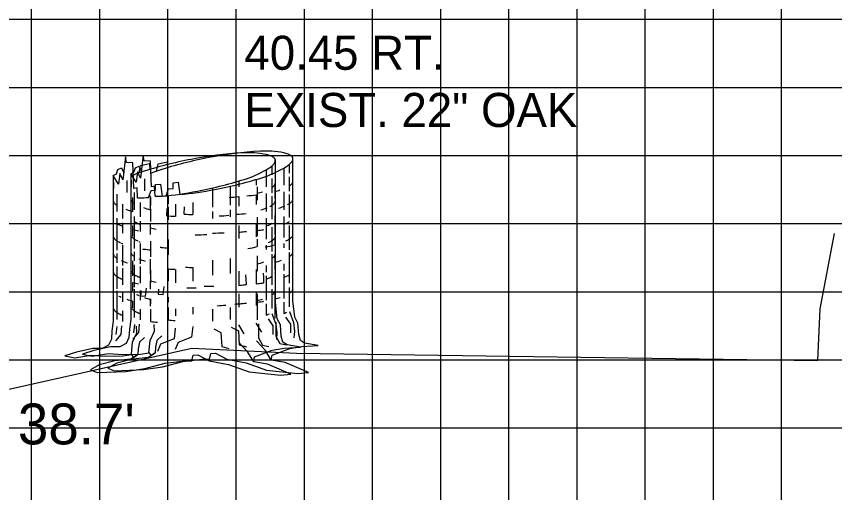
# Model space of a CAD drawing. Extents: x 853785 to 853955, y 366268 to 366378.
# Drawn here: x 853907.21 to 853919.21, y 366284.29 to 366291.28 of the extents above; entities that cross this region are included whole.
import ezdxf

# ---------------------------------------------------------------- set-up
doc = ezdxf.new("R2010")
doc.units = 0
for name, color, linetype in [('D_Text_Monospaced', 7, 'Continuous'), ('D_Text_Standard', 7, 'Continuous'), ('MAJOR', 7, 'Continuous'), ('MINOR', 7, 'Continuous'), ('S_Roadway_Centerline', 7, 'Continuous'), ('S_Trees_Decid_Pay', 7, 'Continuous')]:
    doc.layers.add(name, color=color, linetype=linetype)

msp = doc.modelspace()

# ---------------------------------------------------------------- linework, layer by layer
at = {"layer": 'MAJOR'}
for p, q in [((853908.435, 366277.236), (853908.435, 366297.236)), ((853913.435, 366277.236), (853913.435, 366297.236)), ((853918.435, 366277.236), (853918.435, 366297.236)), ((853798.435, 366287.236), (853938.435, 366287.236))]:
    msp.add_line(p, q, dxfattribs=at)
at = {"layer": 'MINOR'}
for p, q in [((853907.435, 366277.236), (853907.435, 366297.236)), ((853909.435, 366277.236), (853909.435, 366297.236)), ((853910.435, 366277.236), (853910.435, 366297.236)), ((853911.435, 366277.236), (853911.435, 366297.236)), ((853912.435, 366277.236), (853912.435, 366297.236)), ((853914.435, 366277.236), (853914.435, 366297.236)), ((853915.435, 366277.236), (853915.435, 366297.236)), ((853916.435, 366277.236), (853916.435, 366297.236)), ((853917.435, 366277.236), (853917.435, 366297.236)), ((853798.435, 366291.236), (853938.435, 366291.236)), ((853798.435, 366290.236), (853938.435, 366290.236)), ((853798.435, 366289.236), (853938.435, 366289.236)), ((853798.435, 366288.236), (853938.435, 366288.236)), ((853798.435, 366286.236), (853938.435, 366286.236)), ((853798.435, 366285.236), (853938.435, 366285.236))]:
    msp.add_line(p, q, dxfattribs=at)
at = {"layer": 'S_Roadway_Centerline'}
msp.add_lwpolyline([(853837.576, 366284.644), (853850.621, 366285.197), (853857.775, 366285.567), (853862.721, 366285.439), (853868.661, 366285.302), (853871.998, 366285.204), (853882.091, 366284.926), (853892.253, 366284.386), (853893.703, 366284.334), (853894.544, 366284.353), (853894.551, 366284.361), (853894.991, 366284.732), (853895.13, 366284.733), (853902.757, 366284.942), (853904.091, 366285.128), (853909.786, 366286.408), (853911.32, 366286.334), (853918.965, 366286.226), (853919.002, 366286.986), (853919.212, 366288.09)], dxfattribs=at)
at = {"layer": 'S_Trees_Decid_Pay'}
for p, q in [((853910.957, 366289.071), (853910.957, 366288.951)), ((853911.214, 366289.096), (853911.214, 366288.975)), ((853910.877, 366289.027), (853910.877, 366288.773)), ((853911.134, 366289.052), (853911.134, 366288.798)), ((853908.832, 366288.868), (853908.832, 366288.693)), ((853909.09, 366288.893), (853909.09, 366288.718)), ((853910.472, 366288.86), (853910.472, 366288.773)), ((853910.73, 366288.885), (853910.73, 366288.798)), ((853910.957, 366288.899), (853910.957, 366288.685)), ((853911.214, 366288.924), (853911.214, 366288.71)), ((853910.089, 366288.759), (853910.089, 366288.479)), ((853910.346, 366288.784), (853910.346, 366288.504)), ((853910.745, 366288.773), (853910.745, 366288.582)), ((853911.002, 366288.798), (853911.002, 366288.607)), ((853908.683, 366288.668), (853908.683, 366288.413)), ((853908.917, 366288.619), (853908.917, 366288.414)), ((853908.94, 366288.693), (853908.94, 366288.438)), ((853909.174, 366288.644), (853909.174, 366288.439)), ((853909.178, 366288.621), (853909.178, 366288.502)), ((853909.436, 366288.646), (853909.436, 366288.527)), ((853910.472, 366288.632), (853910.472, 366288.493)), ((853910.73, 366288.657), (853910.73, 366288.518)), ((853910.877, 366288.677), (853910.877, 366288.413)), ((853910.957, 366288.64), (853910.957, 366288.302)), ((853911.134, 366288.702), (853911.134, 366288.438)), ((853911.214, 366288.664), (853911.214, 366288.327)), ((853908.769, 366288.522), (853908.769, 366288.31)), ((853909.026, 366288.547), (853909.026, 366288.335)), ((853909.436, 366288.475), (853909.436, 366288.29)), ((853909.543, 366288.522), (853909.543, 366288.342)), ((853909.674, 366288.374), (853909.679, 366288.481)), ((853909.8, 366288.547), (853909.8, 366288.367)), ((853909.178, 366288.45), (853909.178, 366288.265)), ((853909.416, 366288.35), (853909.422, 366288.456)), ((853910.089, 366288.413), (853910.089, 366288.31)), ((853910.346, 366288.438), (853910.346, 366288.335)), ((853911.002, 366288.355), (853911.002, 366288.078)), ((853908.683, 366288.316), (853908.683, 366287.847)), ((853908.769, 366288.245), (853908.769, 366288.096)), ((853908.94, 366288.341), (853908.94, 366287.872)), ((853909.026, 366288.269), (853909.026, 366288.121)), ((853909.174, 366288.232), (853909.174, 366288.078)), ((853910.73, 366288.232), (853910.73, 366288.04)), ((853910.745, 366288.331), (853910.745, 366288.053)), ((853910.877, 366288.316), (853910.877, 366288.008)), ((853911.134, 366288.341), (853911.134, 366288.033)), ((853908.917, 366288.207), (853908.917, 366288.053)), ((853910.472, 366288.207), (853910.472, 366288.016)), ((853910.957, 366288.185), (853910.957, 366287.824)), ((853911.214, 366288.21), (853911.214, 366287.849)), ((853909.436, 366288.004), (853909.436, 366287.775)), ((853910.745, 366288.008), (853910.745, 366287.899)), ((853911.002, 366288.033), (853911.002, 366287.924)), ((853908.769, 366287.919), (853908.769, 366287.619)), ((853909.026, 366287.944), (853909.026, 366287.643)), ((853909.178, 366287.979), (853909.178, 366287.75)), ((853910.877, 366287.919), (853910.877, 366287.853)), ((853911.134, 366287.944), (853911.134, 366287.878)), ((853908.683, 366287.796), (853908.683, 366287.662)), ((853908.94, 366287.821), (853908.94, 366287.687)), ((853910.745, 366287.764), (853910.745, 366287.536)), ((853910.957, 366287.787), (853910.957, 366287.338)), ((853911.002, 366287.789), (853911.002, 366287.561)), ((853911.214, 366287.812), (853911.214, 366287.363)), ((853908.917, 366287.69), (853908.917, 366287.47)), ((853908.94, 366287.629), (853908.94, 366287.304)), ((853909.174, 366287.715), (853909.174, 366287.495)), ((853910.089, 366287.699), (853910.089, 366287.478)), ((853910.346, 366287.723), (853910.346, 366287.503)), ((853911.134, 366287.643), (853911.134, 366287.546)), ((853908.683, 366287.604), (853908.683, 366287.279)), ((853908.769, 366287.581), (853908.769, 366287.338)), ((853909.026, 366287.606), (853909.026, 366287.363)), ((853909.178, 366287.552), (853909.178, 366287.367)), ((853909.436, 366287.577), (853909.436, 366287.392)), ((853909.543, 366287.564), (853909.543, 366287.367)), ((853909.8, 366287.589), (853909.8, 366287.392)), ((853910.472, 366287.536), (853910.472, 366287.328)), ((853910.73, 366287.561), (853910.73, 366287.353)), ((853910.877, 366287.619), (853910.877, 366287.521)), ((853909.174, 366287.395), (853909.174, 366287.275)), ((853910.877, 366287.47), (853910.877, 366287.11)), ((853911.134, 366287.495), (853911.134, 366287.135)), ((853908.917, 366287.371), (853908.917, 366287.25)), ((853908.94, 366287.275), (853908.94, 366286.855)), ((853910.957, 366287.273), (853910.957, 366286.991)), ((853911.214, 366287.298), (853911.214, 366287.015)), ((853908.683, 366287.25), (853908.683, 366286.83)), ((853908.769, 366287.227), (853908.769, 366287.087)), ((853909.026, 366287.252), (853909.026, 366287.112)), ((853909.436, 366287.157), (853909.436, 366287.08)), ((853910.472, 366287.206), (853910.472, 366287.007)), ((853910.73, 366287.231), (853910.73, 366287.032)), ((853910.745, 366287.206), (853910.745, 366286.823)), ((853911.002, 366287.231), (853911.002, 366286.848)), ((853908.917, 366287.099), (853908.917, 366287)), ((853909.174, 366287.124), (853909.174, 366287.025)), ((853909.178, 366287.132), (853909.178, 366287.056)), ((853910.877, 366287.058), (853910.877, 366286.892)), ((853911.134, 366287.083), (853911.134, 366286.916)), ((853908.769, 366286.955), (853908.769, 366286.799)), ((853909.026, 366286.98), (853909.026, 366286.824)), ((853909.178, 366286.978), (853909.178, 366286.805)), ((853909.436, 366287.003), (853909.436, 366286.83)), ((853909.543, 366286.984), (853909.543, 366286.881)), ((853909.8, 366287.009), (853909.8, 366286.906)), ((853910.089, 366286.978), (853910.089, 366286.805)), ((853910.346, 366287.003), (853910.346, 366286.83)), ((853908.686, 366286.727), (853908.672, 366286.609)), ((853908.943, 366286.752), (853908.929, 366286.634)), ((853910.468, 366286.75), (853910.548, 366286.618)), ((853910.725, 366286.775), (853910.805, 366286.643))]:
    msp.add_line(p, q, dxfattribs=at)
for points in [[(853908.89, 366288.967), (853908.89, 366286.83), (853908.869, 366286.688), (853908.863, 366286.562), (853908.82, 366286.475), (853908.728, 366286.426), (853908.592, 366286.426), (853908.348, 366286.37), (853908.182, 366286.321), (853908.324, 366286.29), (853908.561, 366286.328), (853908.771, 366286.315), (853909.032, 366286.321), (853909.156, 366286.34), (853909.186, 366286.297), (853909.249, 366286.34), (853909.149, 366286.272), (853908.915, 366286.247), (853908.684, 366286.185), (853908.554, 366286.115), (853908.653, 366286.072), (853909.075, 366286.091), (853909.354, 366286.134), (853909.652, 366286.21), (853909.938, 366286.247), (853910.043, 366286.247), (853910.062, 366286.328), (853910.13, 366286.334), (853910.296, 366286.247), (853910.583, 366286.191), (853910.881, 366286.084), (853911.34, 366286.035), (853911.495, 366286.048), (853911.153, 366286.198), (853910.949, 366286.229), (853910.961, 366286.303), (853911.221, 366286.402), (853911.396, 366286.433), (853911.637, 366286.445), (853911.439, 366286.482), (853911.377, 366286.519), (853911.353, 366286.605), (853911.34, 366286.775), (853911.295, 366286.861), (853911.267, 366287.101), (853911.267, 366289.187)], [(853908.989, 366288.615), (853908.981, 366288.759), (853908.935, 366288.751), (853908.921, 366289.126), (853908.827, 366289.134), (853908.812, 366289.214), (853908.775, 366288.876), (853908.729, 366288.971), (853908.709, 366288.817), (853908.632, 366288.942), (853908.638, 366288.752)], [(853909.246, 366288.639), (853909.238, 366288.784), (853909.193, 366288.776), (853909.178, 366289.151), (853909.084, 366289.159), (853909.069, 366289.239), (853909.032, 366288.901), (853908.987, 366288.996), (853908.966, 366288.842), (853908.89, 366288.967), (853908.896, 366288.777)], [(853908.632, 366288.942), (853908.632, 366286.805), (853908.612, 366286.663), (853908.606, 366286.537), (853908.563, 366286.451), (853908.47, 366286.401), (853908.334, 366286.401), (853908.091, 366286.346), (853907.924, 366286.296), (853908.067, 366286.266), (853908.304, 366286.303), (853908.514, 366286.29), (853908.775, 366286.296), (853908.899, 366286.315), (853908.929, 366286.272), (853908.991, 366286.315), (853908.892, 366286.247), (853908.657, 366286.222), (853908.427, 366286.161), (853908.297, 366286.09), (853908.396, 366286.047), (853908.818, 366286.066), (853909.096, 366286.109), (853909.395, 366286.185), (853909.681, 366286.222), (853909.786, 366286.222), (853909.804, 366286.303), (853909.873, 366286.309), (853910.039, 366286.222), (853910.325, 366286.166), (853910.624, 366286.06), (853911.083, 366286.01), (853911.237, 366286.023), (853910.895, 366286.173), (853910.692, 366286.204), (853910.704, 366286.278), (853910.964, 366286.377), (853911.139, 366286.408), (853911.38, 366286.42), (853911.182, 366286.457), (853911.12, 366286.494), (853911.096, 366286.581), (853911.083, 366286.75), (853911.038, 366286.836), (853911.01, 366287.077), (853911.01, 366289.163)], [(853908.89, 366288.967), (853908.936, 366288.99), (853908.958, 366289.056), (853909.01, 366289.078), (853909.043, 366289.004)], [(853909.011, 366288.981), (853909.032, 366289.088), (853909.164, 366289.119), (853909.171, 366289.031)], [(853909.268, 366289.006), (853909.289, 366289.113), (853909.421, 366289.144), (853909.428, 366289.056)], [(853908.632, 366288.942), (853908.678, 366288.965), (853908.701, 366289.031), (853908.752, 366289.054), (853908.786, 366288.979)], [(853909.407, 366288.644), (853909.444, 366288.747), (853909.51, 366288.753), (853909.51, 366288.835), (853909.584, 366288.842), (853909.609, 366288.661)], [(853909.15, 366288.619), (853909.187, 366288.722), (853909.252, 366288.728), (853909.252, 366288.81), (853909.327, 366288.817), (853909.352, 366288.636)], [(853910.843, 366287.367), (853910.842, 366287.443), (853910.834, 366287.51)], [(853910.586, 366287.342), (853910.584, 366287.418), (853910.577, 366287.485)], [(853909.04, 366287.25), (853909.032, 366287.176), (853909.106, 366287.17), (853909.121, 366287.287)], [(853909.298, 366287.275), (853909.289, 366287.201), (853909.363, 366287.195), (853909.378, 366287.311)], [(853910.959, 366286.918), (853911.019, 366286.758), (853911.033, 366286.632), (853911.025, 366286.535)], [(853911.216, 366286.943), (853911.277, 366286.783), (853911.291, 366286.657), (853911.283, 366286.56)], [(853910.902, 366286.838), (853910.974, 366286.735), (853910.974, 366286.609)], [(853911.019, 366286.788), (853911.019, 366286.583), (853911.077, 366286.473), (853911.174, 366286.457)], [(853911.159, 366286.863), (853911.231, 366286.76), (853911.231, 366286.634)], [(853908.752, 366286.735), (853908.746, 366286.609), (853908.664, 366286.515)], [(853908.899, 366286.315), (853908.917, 366286.494), (853908.979, 366286.63), (853908.972, 366286.731)], [(853909.01, 366286.76), (853909.003, 366286.634), (853908.921, 366286.54)], [(853909.156, 366286.34), (853909.174, 366286.519), (853909.236, 366286.655), (853909.23, 366286.756)], [(853909.541, 366286.698), (853909.524, 366286.544), (853909.327, 366286.463), (853909.281, 366286.36)], [(853909.798, 366286.723), (853909.781, 366286.569), (853909.584, 366286.488), (853909.539, 366286.385)], [(853910.107, 366286.689), (853910.21, 366286.638), (853910.224, 366286.432), (853910.327, 366286.403)], [(853910.364, 366286.714), (853910.467, 366286.663), (853910.481, 366286.457), (853910.585, 366286.428)], [(853910.762, 366286.764), (853910.762, 366286.558), (853910.819, 366286.449), (853910.916, 366286.432)], [(853909.09, 366286.562), (853909.016, 366286.494), (853908.997, 366286.395), (853908.991, 366286.315)], [(853909.347, 366286.587), (853909.273, 366286.519), (853909.254, 366286.42), (853909.249, 366286.34)], [(853910.692, 366286.204), (853910.605, 366286.346), (853910.474, 366286.488)], [(853910.949, 366286.229), (853910.863, 366286.37), (853910.731, 366286.513)]]:
    msp.add_lwpolyline(points, dxfattribs=at)
for centre, radius, start, end in [((853911.18, 366283.186), 6.126, 100.7779, 107.8613), ((853910.922, 366283.161), 6.126, 93.6944, 100.7779), ((853911.18, 366283.186), 6.126, 93.6944, 100.7779), ((853910.611, 366287.977), 1.299, 78.2779, 93.6944), ((853910.869, 366288.002), 1.299, 78.2779, 93.6944), ((853910.778, 366288.78), 0.48, 69.9843, 78.2779), ((853910.886, 366289.077), 0.164, 55.7779, 69.9843), ((853910.918, 366289.123), 0.107, 45.9547, 55.7779), ((853910.948, 366289.154), 0.0645, 33.2779, 45.9547), ((853910.956, 366289.16), 0.0544, 22.46, 33.2779), ((853911.035, 366288.805), 0.48, 69.9843, 78.2779), ((853911.143, 366289.101), 0.164, 55.7779, 69.9843), ((853911.175, 366289.148), 0.107, 45.9547, 55.7779), ((853911.205, 366289.179), 0.0645, 33.2779, 45.9547), ((853911.213, 366289.185), 0.0544, 22.46, 33.2779), ((853911.22, 366289.188), 0.0467, 10.7779, 22.46), ((853911.22, 366289.188), 0.0467, 359.0957, 10.7779), ((853911.213, 366289.188), 0.0544, 348.2779, 359.0957), ((853910.922, 366283.161), 6.126, 100.7779, 107.8613), ((853910.458, 366290.161), 1.299, 287.8613, 303.2779), ((853910.65, 366289.45), 0.48, 303.2779, 311.5714), ((853910.86, 366289.214), 0.164, 311.5714, 325.7779), ((853910.907, 366289.183), 0.107, 325.7779, 335.6011), ((853910.945, 366289.165), 0.0645, 335.6011, 348.2779), ((853910.963, 366289.163), 0.0467, 10.7779, 22.46), ((853910.963, 366289.163), 0.0467, 359.0957, 10.7779), ((853910.955, 366289.163), 0.0544, 348.2779, 359.0957), ((853910.908, 366289.475), 0.48, 303.2779, 311.5714), ((853911.117, 366289.239), 0.164, 311.5714, 325.7779), ((853911.164, 366289.207), 0.107, 325.7779, 335.6011), ((853911.203, 366289.19), 0.0645, 335.6011, 348.2779), ((853909.442, 366287.755), 1.299, 107.8613, 113.3069), ((853909.699, 366287.78), 1.299, 107.8613, 113.3069), ((853910.2, 366290.136), 1.299, 287.8613, 303.2779), ((853908.72, 366294.73), 6.126, 280.7779, 287.8613), ((853908.977, 366294.754), 6.126, 280.7779, 287.8613), ((853911.168, 366288.89), 0.109, 315, 324.8263), ((853911.203, 366288.865), 0.0657, 324.8263, 337.5), ((853911.213, 366288.861), 0.0554, 337.5, 348.3185), ((853908.72, 366294.73), 6.126, 275.9147, 280.7779), ((853908.977, 366294.754), 6.126, 275.9147, 280.7779), ((853910.87, 366288.906), 0.166, 301.67, 315), ((853910.911, 366288.865), 0.109, 315, 324.8263), ((853910.946, 366288.84), 0.0657, 324.8263, 337.5), ((853910.655, 366289.95), 1.292, 285.5651, 289.0916), ((853910.955, 366288.836), 0.0554, 337.5, 348.3185), ((853911.127, 366288.93), 0.166, 301.67, 315), ((853908.937, 366288.599), 0.0476, 180, 191.6815), ((853908.945, 366288.6), 0.0554, 191.6815, 202.5), ((853909.031, 366289.913), 1.299, 268.1289, 273.6944), ((853908.72, 366294.73), 6.126, 273.6944, 274.0246), ((853909.288, 366289.938), 1.299, 268.1289, 273.6944), ((853908.977, 366294.754), 6.126, 273.6944, 274.0246), ((853909.822, 366294.513), 5.916, 274.9515, 276.3087), ((853910.079, 366294.538), 5.916, 274.9515, 276.3087), ((853910.398, 366289.925), 1.292, 285.5651, 289.0916), ((853911.212, 366288.6), 0.0554, 337.5, 348.3185), ((853908.68, 366288.574), 0.0476, 180, 191.6815), ((853908.688, 366288.575), 0.0554, 191.6815, 202.5), ((853908.697, 366288.579), 0.0657, 202.5, 215.1737), ((853908.733, 366288.604), 0.109, 215.1737, 225), ((853908.773, 366288.645), 0.166, 225, 239.1924), ((853908.955, 366288.604), 0.0657, 202.5, 215.1737), ((853908.99, 366288.629), 0.109, 215.1737, 225), ((853909.031, 366288.67), 0.166, 225, 239.1924), ((853909.503, 366289.689), 1.292, 250.6119, 255.2856), ((853910.397, 366289.664), 1.292, 288.0829, 292.5), ((853910.706, 366288.918), 0.484, 297.4162, 300.8076), ((853910.869, 366288.645), 0.166, 300.8076, 315), ((853910.91, 366288.604), 0.109, 315, 324.8263), ((853910.945, 366288.579), 0.0657, 324.8263, 337.5), ((853910.955, 366288.575), 0.0554, 337.5, 348.3185), ((853910.654, 366289.689), 1.292, 288.0829, 292.5), ((853910.964, 366288.943), 0.484, 297.4162, 300.8076), ((853911.126, 366288.67), 0.166, 300.8076, 315), ((853911.167, 366288.629), 0.109, 315, 324.8263), ((853911.202, 366288.604), 0.0657, 324.8263, 337.5), ((853909.245, 366289.664), 1.292, 250.6119, 255.2856), ((853909.821, 366294.252), 5.916, 266.0776, 267.3043), ((853910.078, 366294.277), 5.916, 266.0776, 267.3043), ((853909.821, 366294.252), 5.916, 273.5382, 274.8924), ((853910.078, 366294.277), 5.916, 273.5382, 274.8924), ((853908.773, 366288.381), 0.166, 237.0378, 239.1924), ((853908.936, 366288.654), 0.484, 239.1924, 247.5), ((853909.031, 366288.406), 0.166, 237.0378, 239.1924), ((853909.193, 366288.679), 0.484, 239.1924, 247.5), ((853909.503, 366289.425), 1.292, 247.5, 248.3537), ((853910.706, 366288.654), 0.484, 292.5, 300.8076), ((853910.869, 366288.381), 0.166, 300.8076, 301.6001), ((853910.654, 366289.425), 1.292, 291.8071, 292.5), ((853910.964, 366288.679), 0.484, 292.5, 300.8076), ((853911.126, 366288.406), 0.166, 300.8076, 301.6001), ((853909.245, 366289.4), 1.292, 247.5, 248.3537), ((853909.245, 366289.4), 1.292, 255.2856, 259.2632), ((853909.503, 366289.425), 1.292, 255.2856, 259.2632), ((853909.821, 366293.988), 5.916, 276.3184, 277.1546), ((853910.397, 366289.4), 1.292, 277.1546, 278.3662), ((853910.078, 366294.013), 5.916, 276.3184, 277.1546), ((853910.654, 366289.425), 1.292, 277.1546, 278.3662), ((853910.397, 366289.4), 1.292, 291.8071, 292.5), ((853908.68, 366288.053), 0.0476, 180, 191.6815), ((853908.688, 366288.054), 0.0554, 191.6815, 202.5), ((853908.697, 366288.058), 0.0657, 202.5, 215.1737), ((853908.733, 366288.083), 0.109, 215.1737, 225), ((853908.773, 366288.124), 0.166, 225, 239.1924), ((853908.937, 366288.078), 0.0476, 180, 191.6815), ((853908.945, 366288.079), 0.0554, 191.6815, 202.5), ((853908.955, 366288.083), 0.0657, 202.5, 215.1737), ((853908.99, 366288.108), 0.109, 215.1737, 225), ((853909.031, 366288.149), 0.166, 225, 239.1924), ((853909.193, 366288.422), 0.484, 239.1924, 245.7725), ((853909.821, 366293.988), 5.916, 270.1162, 271.7708), ((853910.078, 366294.013), 5.916, 270.1162, 271.7708), ((853910.869, 366288.124), 0.166, 300.8076, 315), ((853910.91, 366288.083), 0.109, 315, 324.8263), ((853910.945, 366288.058), 0.0657, 324.8263, 337.5), ((853910.955, 366288.054), 0.0554, 337.5, 348.3185), ((853910.964, 366288.422), 0.484, 294.6372, 300.8076), ((853911.126, 366288.149), 0.166, 300.8076, 315), ((853911.167, 366288.108), 0.109, 315, 324.8263), ((853911.202, 366288.083), 0.0657, 324.8263, 337.5), ((853911.212, 366288.079), 0.0554, 337.5, 348.3185), ((853908.936, 366288.397), 0.484, 239.1924, 245.7725), ((853909.245, 366289.143), 1.292, 247.5, 248.4842), ((853909.503, 366289.168), 1.292, 247.5, 248.4842), ((853909.503, 366289.168), 1.292, 261.8726, 262.8454), ((853910.078, 366293.756), 5.916, 262.8454, 263.7595), ((853910.397, 366289.143), 1.292, 279.2565, 285.6105), ((853910.654, 366289.168), 1.292, 279.2565, 285.6105), ((853910.706, 366288.397), 0.484, 294.6372, 300.8076), ((853908.68, 366287.795), 0.0476, 180, 191.6815), ((853908.688, 366287.797), 0.0554, 191.6815, 202.5), ((853908.697, 366287.801), 0.0657, 202.5, 215.1737), ((853908.733, 366287.826), 0.109, 215.1737, 225), ((853908.773, 366287.867), 0.166, 225, 239.1924), ((853908.937, 366287.82), 0.0476, 180, 191.6815), ((853908.945, 366287.822), 0.0554, 191.6815, 202.5), ((853908.955, 366287.826), 0.0657, 202.5, 215.1737), ((853908.99, 366287.851), 0.109, 215.1737, 225), ((853909.031, 366287.891), 0.166, 225, 239.1924), ((853909.245, 366289.143), 1.292, 261.8726, 262.8454), ((853909.821, 366293.731), 5.916, 262.8454, 263.7595), ((853910.869, 366287.867), 0.166, 302.0694, 315), ((853910.91, 366287.826), 0.109, 315, 324.8263), ((853910.945, 366287.801), 0.0657, 324.8263, 337.5), ((853910.955, 366287.797), 0.0554, 337.5, 348.3185), ((853911.126, 366287.891), 0.166, 302.0694, 315), ((853911.167, 366287.851), 0.109, 315, 324.8263), ((853911.202, 366287.826), 0.0657, 324.8263, 337.5), ((853911.212, 366287.822), 0.0554, 337.5, 348.3185), ((853909.245, 366288.886), 1.292, 247.5, 251.799), ((853909.503, 366288.911), 1.292, 247.5, 251.799), ((853910.397, 366288.886), 1.292, 285.6105, 290.1001), ((853910.654, 366288.911), 1.292, 285.6105, 290.1001), ((853908.68, 366287.53), 0.0476, 180, 191.6815), ((853908.688, 366287.531), 0.0554, 191.6815, 202.5), ((853908.697, 366287.535), 0.0657, 202.5, 215.1737), ((853908.937, 366287.555), 0.0476, 180, 191.6815), ((853908.945, 366287.556), 0.0554, 191.6815, 202.5), ((853908.955, 366287.56), 0.0657, 202.5, 215.1737), ((853908.99, 366287.585), 0.109, 215.1737, 225), ((853909.031, 366287.626), 0.166, 225, 239.1924), ((853909.821, 366293.474), 5.916, 266.2721, 267.3043), ((853910.078, 366293.499), 5.916, 266.2721, 267.3043), ((853910.955, 366287.531), 0.0554, 337.5, 348.3185), ((853911.212, 366287.556), 0.0554, 337.5, 348.3185), ((853908.733, 366287.56), 0.109, 215.1737, 225), ((853908.773, 366287.601), 0.166, 225, 239.1924), ((853908.936, 366287.874), 0.484, 239.1924, 247.5), ((853909.245, 366288.62), 1.292, 247.5, 248.3537), ((853909.193, 366287.899), 0.484, 239.1924, 247.5), ((853909.503, 366288.645), 1.292, 247.5, 248.3537), ((853909.503, 366288.645), 1.292, 255.2856, 259.2463), ((853910.706, 366287.874), 0.484, 292.5, 300.8076), ((853910.869, 366287.601), 0.166, 300.8076, 302.0694), ((853910.964, 366287.899), 0.484, 292.5, 300.8076), ((853911.126, 366287.626), 0.166, 300.8076, 302.0694), ((853909.245, 366288.62), 1.292, 255.2856, 259.2463), ((853909.821, 366293.208), 5.916, 268.9207, 270), ((853909.821, 366293.208), 5.916, 270, 270.2757), ((853910.078, 366293.233), 5.916, 268.9207, 270), ((853910.078, 366293.233), 5.916, 270, 270.2757), ((853909.821, 366293.208), 5.916, 276.3184, 277.1546), ((853910.397, 366288.62), 1.292, 277.1546, 278.3795), ((853910.078, 366293.233), 5.916, 276.3184, 277.1546), ((853910.654, 366288.645), 1.292, 277.1546, 278.3795), ((853911.212, 366287.284), 0.0554, 337.5, 348.3185), ((853908.936, 366287.602), 0.484, 242.734, 247.5), ((853909.193, 366287.627), 0.484, 242.734, 247.5), ((853909.503, 366288.373), 1.292, 251.3664, 255.2856), ((853910.869, 366287.329), 0.166, 302.0694, 315), ((853910.91, 366287.289), 0.109, 315, 324.8263), ((853910.945, 366287.264), 0.0657, 324.8263, 337.5), ((853910.654, 366288.373), 1.292, 285.6105, 289.1534), ((853910.955, 366287.26), 0.0554, 337.5, 348.3185), ((853911.126, 366287.354), 0.166, 302.0694, 315), ((853911.167, 366287.313), 0.109, 315, 324.8263), ((853911.202, 366287.288), 0.0657, 324.8263, 337.5), ((853909.245, 366288.348), 1.292, 251.3664, 255.2856), ((853908.937, 366287.026), 0.0476, 180, 191.6815), ((853909.821, 366292.936), 5.916, 273.2637, 274.461), ((853910.078, 366292.961), 5.916, 273.2637, 274.461), ((853909.821, 366292.936), 5.916, 276.3184, 277.1546), ((853910.397, 366288.348), 1.292, 277.1546, 278.3662), ((853910.078, 366292.961), 5.916, 276.3184, 277.1546), ((853910.397, 366288.348), 1.292, 285.6105, 289.1534), ((853910.654, 366288.373), 1.292, 277.1546, 278.3662), ((853908.68, 366287.001), 0.0476, 180, 191.6815), ((853908.688, 366287.002), 0.0554, 191.6815, 202.5), ((853908.697, 366287.006), 0.0657, 202.5, 215.1737), ((853908.733, 366287.031), 0.109, 215.1737, 225), ((853908.773, 366287.072), 0.166, 225, 239.1924), ((853908.936, 366287.345), 0.484, 239.1924, 247.5), ((853908.945, 366287.027), 0.0554, 191.6815, 202.5), ((853908.955, 366287.031), 0.0657, 202.5, 215.1737), ((853908.99, 366287.056), 0.109, 215.1737, 225), ((853909.031, 366287.097), 0.166, 225, 239.1924), ((853909.193, 366287.37), 0.484, 239.1924, 247.5), ((853909.503, 366288.116), 1.292, 247.5, 248.3537), ((853910.706, 366287.345), 0.484, 292.5, 296.5499), ((853910.664, 366288.12), 1.292, 291.3696, 292.0604), ((853910.964, 366287.37), 0.484, 292.5, 296.5499), ((853909.245, 366288.091), 1.292, 247.5, 248.3537), ((853909.821, 366292.679), 5.916, 263.7831, 264.7656), ((853910.078, 366292.704), 5.916, 263.7831, 264.7656), ((853910.406, 366288.095), 1.292, 291.3696, 292.0604)]:
    msp.add_arc(centre, radius, start, end, dxfattribs=at)

# ---------------------------------------------------------------- texts
at = {"layer": 'D_Text_Monospaced'}
for s, height, p in [('40.45 RT.', 0.5, (853910.556, 366290.494)), ('EXIST. 22" OAK', 0.49998, (853910.556, 366289.654))]:
    msp.add_text(s, height=height, dxfattribs=at).set_placement(p)
at = {"layer": 'D_Text_Standard'}
msp.add_text("38.7'", height=0.6, dxfattribs=at).set_placement((853907.234, 366284.994))

doc.saveas('drawing.dxf')
